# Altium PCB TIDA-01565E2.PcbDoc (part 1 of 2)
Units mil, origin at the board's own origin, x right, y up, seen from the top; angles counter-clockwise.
Board outline 1450 x 4000 mil, 4 copper layers (Top Layer L1, GND L2, Power L3, Bottom Layer L4), stack 62.4 mil thick; 92 components, 39 nets, 230 pads, 175 vias.
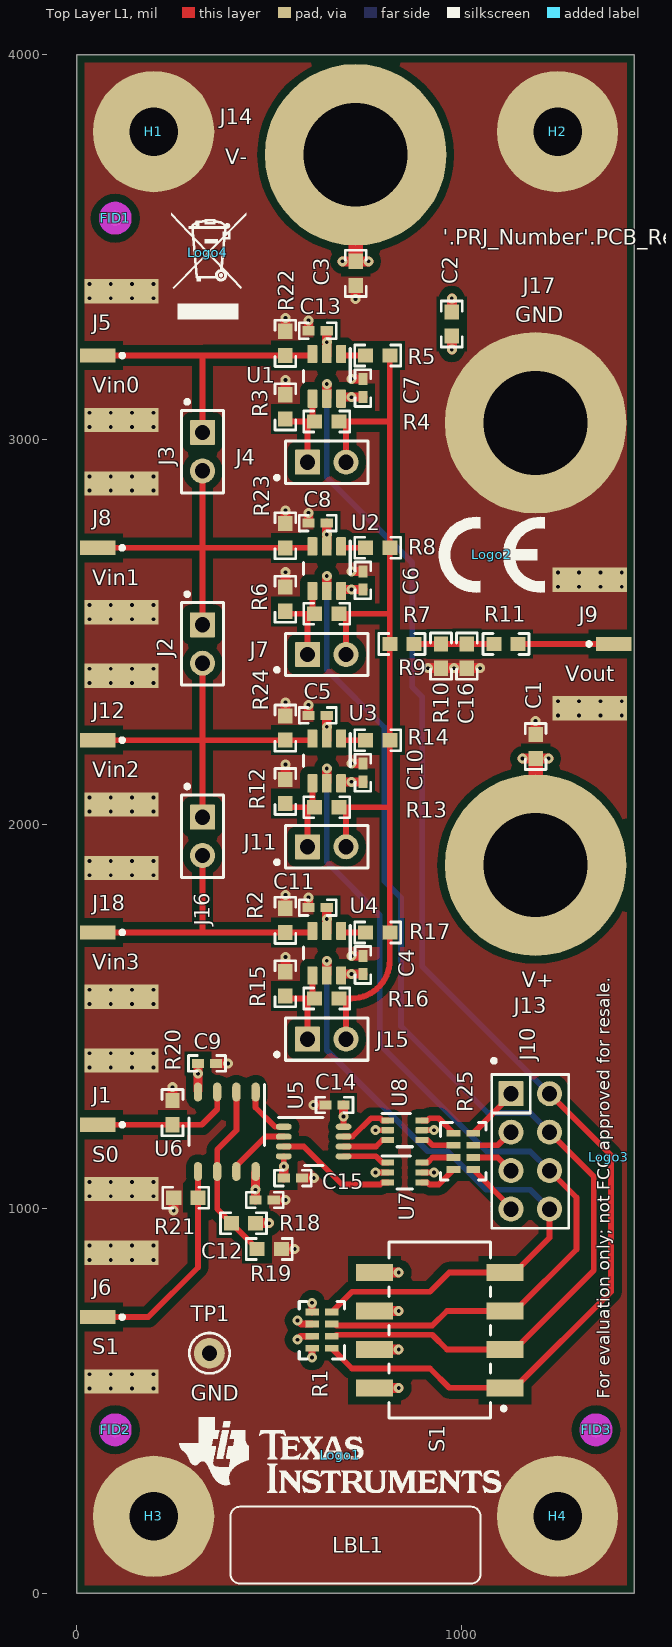
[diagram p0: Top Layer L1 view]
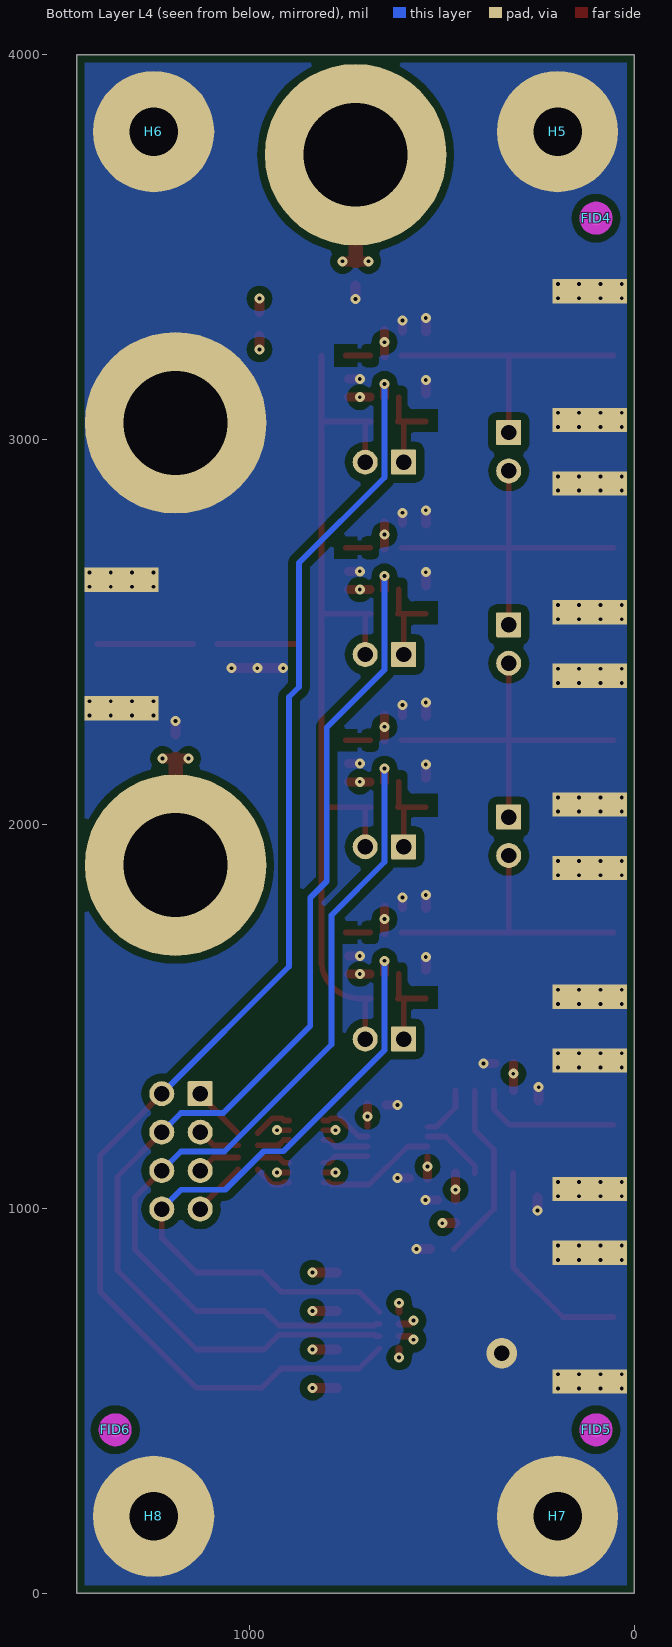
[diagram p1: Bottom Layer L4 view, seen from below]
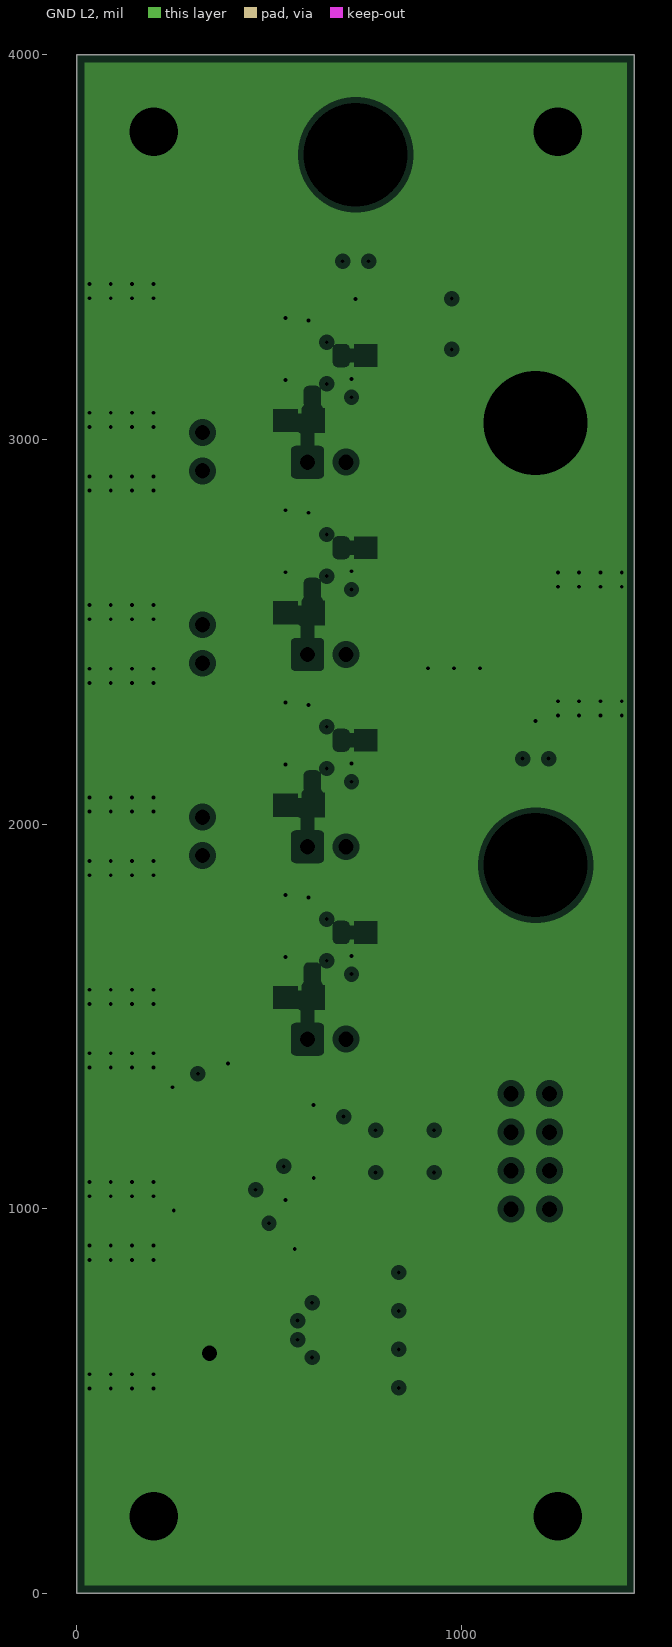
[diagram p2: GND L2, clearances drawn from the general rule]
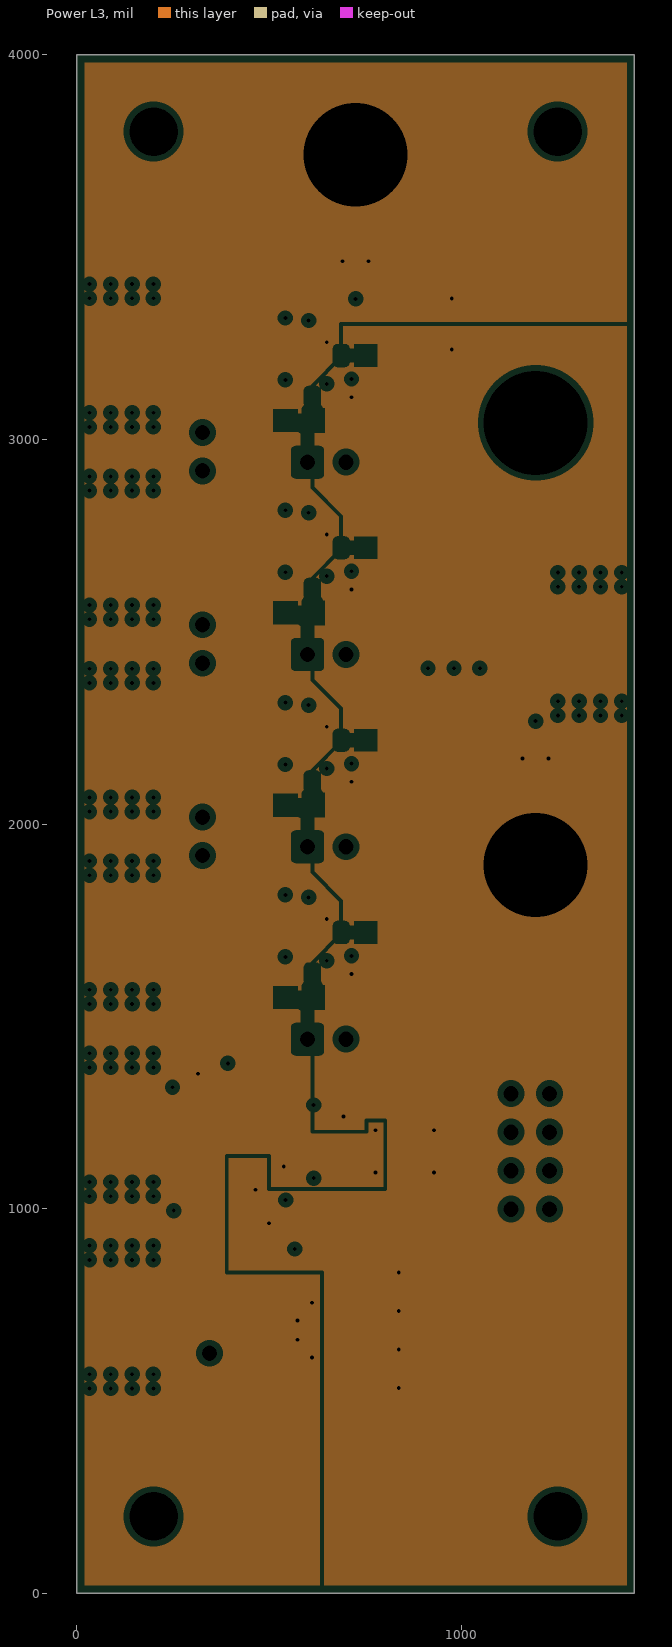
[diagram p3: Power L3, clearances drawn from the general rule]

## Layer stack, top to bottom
Top Solder: solder mask 0.4, Solder Resist, Dk 3.5
Top Layer L1: signal copper 1.4
Dielectric 1: core 8.4, FR-4 High Tg, Dk 4.6
GND L2: plane copper 1.4, net GND
Dielectric 2: prepreg 40, FR-4 High Tg, Dk 4.6
Power L3: plane copper 1.4, net (Multiple Nets)
Dielectric 3: core 8.4, FR-4 High Tg, Dk 4.6
Bottom Layer L4: signal copper 1.4
Bottom Solder: solder mask 0.4, Solder Resist, Dk 3.5

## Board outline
0,0 1450,0 1450,4000 0,4000

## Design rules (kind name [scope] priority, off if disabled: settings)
AcuteAngle [All] p1: minimum=4.50000000000000E+0001 checktracksonly=FALSE
AssemblyTestPointUsage [All] p1: valid=2
BoardOutlineClearance BoardOutlineClearance_1 [HasFootprint('Amphenol_901-10309')] p1: gap=20 ignorepadtopadclearanceinfootprint=FALSE except(7.87: SMDPad-OutlineEdge)
BoardOutlineClearance BoardOutlineClearance_MountingHoles [OnCopper and InComponentClass('Mounting Holes')] p2: gap=40 ignorepadtopadclearanceinfootprint=FALSE
BoardOutlineClearance BoardOutlineClearance_Poly [OnCopper and IsPoly] p3: gap=20 ignorepadtopadclearanceinfootprint=FALSE
BoardOutlineClearance [OnCopper and Not InComponentClass('Logo') and not InComponentClass('FiducialMark') and not InRegion(1000,500,4000,800) and not InPoly] p4: gap=20 ignorepadtopadclearanceinfootprint=FALSE
Clearance Clearance_FiducialMark [IsKeepOut and InComponentClass('FiducialMark') vs IsPad and InComponentClass('FiducialMark')] p1: gap=0 ignorepadtopadclearanceinfootprint=FALSE
Clearance Clearance_Keepouts [((IsTrack Or IsArc) And Not InPoly) And IsFree and IsKeepOut vs ((IsTrack Or IsArc) And Not InPoly) And IsFree and IsKeepOut] p2: gap=0 ignorepadtopadclearanceinfootprint=FALSE
Clearance Clearance_Poly [InPolygon] p3: gap=20 ignorepadtopadclearanceinfootprint=FALSE except(0: Arc-Hole Track-Hole SMDPad-Hole THPad-Hole Via-Hole Fill-Hole Poly-Hole Region-Hole Text-Hole)
Clearance [All] p4: gap=7.87 ignorepadtopadclearanceinfootprint=FALSE except(0: Arc-Hole Track-Hole SMDPad-Hole THPad-Hole Via-Hole Fill-Hole Poly-Hole Region-Hole Text-Hole)
ComponentClearance ComponentClearance_MountingHoles_FiducialMarks [InComponentClass('Mounting Holes') vs InComponentClass('FiducialMark')] p1: gap=50 collisioncheckmode=3 verticalgap=10 showdistances=FALSE
ComponentClearance ComponentClearance_Shunt [InComponentClass('Header') vs InComponentClass('Shunt')] p2: gap=0 collisioncheckmode=3 verticalgap=0 showdistances=FALSE
ComponentClearance ComponentClearance_Logo [InComponentClass('Logo')] p3: gap=0 collisioncheckmode=3 verticalgap=0 showdistances=FALSE
ComponentClearance ComponentClearance_ScrewToNut [(HasFootprint('NY PMS 440 0025 PH')) vs (HasFootprint('Keystone_1902C'))] p4: gap=5 collisioncheckmode=3 verticalgap=10 showdistances=FALSE
ComponentClearance ComponentClearance_MountingHoles [InComponentClass('Mounting Holes')] p5: gap=69 collisioncheckmode=3 verticalgap=100000 showdistances=FALSE
ComponentClearance ComponentClearance_SmallPassives [HasFootprint('0201*') or HasFootprint('0402*') or HasFootprint('0508') or HasFootprint('0603*') or HasFootprint('0612') or HasFootprint('0805*') or HasFootprint('0815*') or HasFootprint('0830*') or HasFootprint('1206*') or HasFootprint('1210*') or HasFootprint('1808*') or HasFootprint('1812*') or HasFootprint('1825*') or HasFootprint('2010*') or HasFootprint('2220*') or HasFootprint('2225*') or HasFootprint('2512*') or HasFootprint('2728*') or HasFootprint('3518*') or HasFootprint('DBV0006A*') vs HasFootprint('0201*') or HasFootprint('0402*') or HasFootprint('0508') or HasFootprint('0603*') or HasFootprint('0612') or HasFootprint('0805*') or HasFootprint('0815*') or HasFootprint('0830*') or HasFootprint('1206*') or HasFootprint('1210*') or HasFootprint('1808*') or HasFootprint('1812*') or HasFootprint('1825*') or HasFootprint('2010*') or HasFootprint('2220*') or HasFootprint('2225*') or HasFootprint('2512*') or HasFootprint('2728*') or HasFootprint('3518*') or HasFootprint('DBV0006A*')] p6: gap=14.96 collisioncheckmode=3 verticalgap=10 showdistances=FALSE
ComponentClearance ComponentClearance_THtoSMT [IsThruComponent vs IsSMTComponent] p7: gap=25 collisioncheckmode=3 verticalgap=30 showdistances=FALSE
ComponentClearance ComponentClearance_THtoTH [IsThruComponent vs IsThruComponent] p8: gap=30 collisioncheckmode=3 verticalgap=30 showdistances=FALSE
ComponentClearance [All] p9: gap=25 collisioncheckmode=3 verticalgap=10 showdistances=FALSE
DiffPairsRouting [All] p1: maxlimit=100 minlimit=10 mostfreqgap=10 toplayer_minwidth=15 toplayer_maxwidth=15 toplayer_prefwidth=15 bottomlayer_minwidth=15 bottomlayer_maxwidth=15 bottomlayer_prefwidth=15 maxuncoupledlength=1000
FabricationTestPointUsage TestPointUsage [All] p1: valid=2 allowmultiple=FALSE
FabricationTestpoint Testpoint [All] p1: side=3 testpointundercomponent=TRUE minsize=40 maxsize=100 preferedsize=60 minholesize=0 maxholesize=40 preferedholesize=32 testpointgrid=1 allowsidetop=TRUE allowsidebottom=TRUE usegrid=TRUE gridtolerance=0.01
FanoutControl Fanout_LCC [IsLCC] p1: bgadir=Out bgaviamode=Centered fanoutstyle=Auto fanoutdirection=Alternating viagrid=1 // Fanout_LCC (Default Rule)
FanoutControl Fanout_BGA [IsBGA] p2: bgadir=Out bgaviamode=Centered fanoutstyle=Auto fanoutdirection=Alternating viagrid=1 // Fanout_BGA (Default Rule)
FanoutControl Fanout_Default [All] p4: bgadir=Out bgaviamode=Centered fanoutstyle=Auto fanoutdirection=Alternating viagrid=1 // Fanout_Default (Default Rule)
FanoutControl Fanout_Small [(CompPinCount < 5)] p5: bgadir=Out bgaviamode=Centered fanoutstyle=Auto fanoutdirection=OutThenIn viagrid=1 // Fanout_Small (Default Rule)
HoleSize [All] p1: absolutevalues=TRUE maxlimit=270 minlimit=7.87 maxpercent=80.000 minpercent=20.000
MinimumAnnularRing MinimumAnnularRing_ThermalPadVias [IsVia and InAnyComponent] p1: minimumring=5.91
MinimumAnnularRing [All] p2: minimumring=8
MinimumSolderMaskSliver MinimumSolderMaskSliver_Logo [InComponentClass('Logo') vs InComponentClass('Logo')] p1: minsoldermaskwidth=0.7
MinimumSolderMaskSliver [All] p2: minsoldermaskwidth=3.94
PlaneClearance [All] p1: clearance=15
PlaneConnect [All] p1: planeconnectstyle=Direct reliefexpansion=10 reliefentries=4 reliefconductorwidth=10 reliefairgap=10
PolygonConnect [All] p1: connectstyle=Direct reliefconductorwidth=10 reliefentries=4 polygonreliefangle="90 Angle" airgapwidth=10
RoutingVias ThermalPadVias [IsVia and InAnyComponent] p1: holewidth=7.87 width=19.68 viastyle="Through Hole" minholewidth=7.87 minwidth=19.68 maxholewidth=12.99 maxwidth=23.62
RoutingVias [All] p2: holewidth=16 width=34 viastyle="Through Hole" minholewidth=7.87 minwidth=26 maxholewidth=40 maxwidth=65
SilkToBoardRegionClearance [Not ((IsComment or IsDesignator) And (Hide <> 'False')) and not InRegion(1000,500,4000,800)] p1:
SilkToSilkClearance SilkToSilkClearance_Pb-FreeLogo [(HasFootprint('Pb-Free_Overlay_Medium') OR HasFootprint('Pb-Free_Overlay_Small')) vs (HasFootprint('Pb-Free_Overlay_Medium') OR HasFootprint('Pb-Free_Overlay_Small'))] p1: silktosilkclearance=0
SilkToSilkClearance [All] p2: silktosilkclearance=4
SilkToSolderMaskClearance SilkToComponentPadClearance [(IsPad or IsFill or IsRegion) and InAnycomponent] p1: minsilkscreentomaskgap=5 clearancetoexposedcopper=TRUE
SilkToSolderMaskClearance "Silk to Solder Mask Opening" [All] p2: minsilkscreentomaskgap=4 clearancetoexposedcopper=FALSE
SolderMaskExpansion [All] p1: expansion=1.97
Width [All] p1: maxlimit=100 minlimit=6 preferedwidth=10 checkconnectedcopper=TRUE
14 further rules are at their usual default settings.

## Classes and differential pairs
component class AssemblyNote: ZZ1 ZZ2 ZZ3 ZZ4
component class FiducialMark: FID1 FID2 FID3 FID4 FID5 FID6
component class Header: J2 J3 J4 J7 J10 J11 J15 J16
component class Label: LBL1
component class Logo: Logo1
component class "Mounting Holes": H1 H2 H3 H4

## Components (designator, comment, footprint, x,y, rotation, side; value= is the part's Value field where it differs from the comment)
C1 "Capacitor" 0603 1193,2201.5 r90 top value=22uF
C2 "Capacitor" 0603 975,3300 r90 top value=22uF
C3 "Capacitor" 0603 725,3431.5 r270 top value=22uF
C4 "Capacitor" 0402 743.96,1633.35 r90 top value=0.1uF
C5 "Capacitor" 0402 626.38,2282.43 r180 top value=0.1uF
C6 "Capacitor" 0402 743.96,2633.35 r90 top value=0.1uF
C7 "Capacitor" 0402 743.96,3133.35 r90 top value=0.1uF
C8 "Capacitor" 0402 626.38,2782.43 r180 top value=0.1uF
C9 "Capacitor" 0402 338.58,1377.57 r0 top value=0.1uF
C10 "Capacitor" 0402 743.96,2133.35 r90 top value=0.1uF
C11 "Capacitor" 0402 626.38,1782.43 r180 top value=0.1uF
C12 "Capacitor" 0402 488.62,1022.43 r0 top value=0.1uF
C13 "Capacitor" 0402 626.38,3282.43 r180 top value=0.1uF
C14 "Capacitor" 0402 670.13,1269.41 r0 top value=0.1uF
C15 "Capacitor" 0402 561.87,1079.41 r180 top value=0.1uF
C16 "Capacitor" 0603 1014.34,2436.5 r270 top value=330pF
FID1 "Fiducial" Fiducial10-20 100,3575 r0 top
FID2 "Fiducial" Fiducial10-20 100,425 r0 top
FID3 "Fiducial" Fiducial10-20 1350,425 r0 top
FID4 "Fiducial" Fiducial10-20 100,3575 r0 bottom
FID5 "Fiducial" Fiducial10-20 100,425 r0 bottom
FID6 "Fiducial" Fiducial10-20 1350,425 r0 bottom
H1 "NY PMS 440 0025 PH" "NY PMS 440 0025 PH" 200,3800 r0 top locked
H2 "NY PMS 440 0025 PH" "NY PMS 440 0025 PH" 1250,3800 r0 top locked
H3 "NY PMS 440 0025 PH" "NY PMS 440 0025 PH" 200,200 r0 top locked
H4 "NY PMS 440 0025 PH" "NY PMS 440 0025 PH" 1250,200 r0 top locked
H5 "Nut" Keystone_1902C 200,3800 r180 bottom locked
H6 "Nut" Keystone_1902C 1250,3800 r180 bottom locked
H7 "Nut" Keystone_1902C 200,200 r180 bottom locked
H8 "Nut" Keystone_1902C 1250,200 r180 bottom locked
J1 "S0" Amphenol_901-10309 0,1218 r90 top
J2 "TSW-102-07-G-S" TSW-102-07-X-S 327,2468 r270 top
J3 "TSW-102-07-G-S" TSW-102-07-X-S 327,2968 r270 top
J4 "TSW-102-07-G-S" TSW-102-07-X-S 650,2940.76 r0 top
J5 "Vin0" Amphenol_901-10309 0,3218 r90 top
J6 "S1" Amphenol_901-10309 0,718 r90 top
J7 "TSW-102-07-G-S" TSW-102-07-X-S 650,2440.76 r0 top
J8 "Vin1" Amphenol_901-10309 0,2718 r90 top
J9 "Vout" Amphenol_901-10309 1450,2468 r270 top
J10 "TSW-104-07-G-D" TSW-104-07-G-D 1179,1148.82 r270 top
J11 "TSW-102-07-G-S" TSW-102-07-X-S 650,1940.76 r0 top
J12 "Vin2" Amphenol_901-10309 0,2218 r90 top
J13 "V+" Keystone_6095 1193,1893 r0 top
J14 "V-" Keystone_6095 725,3740 r0 top
J15 "TSW-102-07-G-S" TSW-102-07-X-S 650,1440.76 r0 top
J16 "TSW-102-07-G-S" TSW-102-07-X-S 327,1968 r270 top
J17 "GND" Keystone_6095 1193,3043 r0 top
J18 "Vin3" Amphenol_901-10309 0,1718 r90 top
LBL1 "Size: 0.65\" x 0.20 \"" Label_650x200 724.79,125 r0 top
Logo1 "Texas Instruments" TI_Stacked_Overlay_Small 685,359 r0 top
Logo2 "CE Mark" CE_Mark_5mm 1079,2700 r0 top
Logo3 "FCC disclaimer" FCC_disclaimer 1383,1133 r90 top
Logo4 "WEEE logo" WEEE_Minimum 341,3485 r0 top
R1 "RES_ARRAY_4x1" TC164 637.5,684 r180 top value=10k
R2 "Resistor" 0603 542.46,1749.5 r270 top value=49.9
R3 "RT0603BRD072KL" 0603 542.46,3084.47 r270 top value=2.00k
R4 "RT0603BRD072KL" 0603 650,3046.4 r0 top value=2.00k
R5 "Resistor" 0603 782.44,3218 r0 top value=49.9
R6 "RT0603BRD072KL" 0603 542.46,2584.47 r270 top value=2.00k
R7 "RT0603BRD072KL" 0603 650,2546.4 r0 top value=2.00k
R8 "Resistor" 0603 782.44,2718 r0 top value=49.9
R9 "RC0603FR-071K96L" 0603 845.44,2468 r0 top value=1.96k
R10 "Resistor" 0603 947,2436.5 r90 top value=51.1
R11 "RC0603JR-070RL" 0603 1115.97,2468 r0 top value=0
R12 "RT0603BRD072KL" 0603 542.46,2084.47 r270 top value=2.00k
R13 "RT0603BRD072KL" 0603 650,2043.77 r0 top value=2.00k
R14 "Resistor" 0603 782.44,2218 r0 top value=49.9
R15 "RT0603BRD072KL" 0603 542.46,1584.47 r270 top value=2.00k
R16 "RT0603BRD072KL" 0603 650,1546.4 r0 top value=2.00k
R17 "Resistor" 0603 782.44,1718 r0 top value=49.9
R18 "Resistor" 0603 433.5,962 r180 top value=100k
R19 "Resistor" 0603 500.5,895 r180 top value=49.9
R20 "Resistor" 0603 249,1249.5 r270 top value=49.9
R21 "Resistor" 0603 283.5,1028.5 r0 top value=49.9
R22 "Resistor" 0603 542.46,3249.5 r270 top value=49.9
R23 "Resistor" 0603 542.46,2749.5 r270 top value=49.9
R24 "Resistor" 0603 542.46,2249.5 r270 top value=49.9
R25 "RES_ARRAY_4x1" TC164 1004.98,1148.81 r0 top value=10k
S1 "SW_4SPST" SW_219-4LPST 943.5,684 r180 top
TP1 "GND" Keystone5001 345,624 r90 top
U1 "OPA837IDBVR" DBV0006A_M 650,3163.87 r270 top
U2 "OPA837IDBVR" DBV0006A_M 650,2663.87 r270 top
U3 "OPA837IDBVR" DBV0006A_M 650,2163.87 r270 top
U4 "OPA837IDBVR" DBV0006A_M 650,1663.87 r270 top
U5 "SN74LVC1G139DCTR" DCT0008A_N 616,1174.41 r0 top
U6 "TI-AMP-D6-2-8_D" D0008A_L 390,1200 r270 top
U7 "SN74LVC2G04DCKT" DCK0006A_N 853,1093.81 r0 top
U8 "SN74LVC2G04DCKT" DCK0006A_N 853,1203.81 r0 top
ZZ1 "This Assembly Note is for PCB labels only" AssemblyNoteLabel 185,4484 r0 top
ZZ2 "These assemblies are ESD sensitive, ESD precautions shall be observed." AssemblyNote 185,4375.11 r0 top
ZZ3 "These assemblies must be clean and free from flux and all contaminants. Use of no clean flux is not acceptable." AssemblyNote 185,4286.56 r0 top
ZZ4 "These assemblies must comply with workmanship standards IPC-A-610 Class 2, unless otherwise specified." AssemblyNote 185,4198 r0 top

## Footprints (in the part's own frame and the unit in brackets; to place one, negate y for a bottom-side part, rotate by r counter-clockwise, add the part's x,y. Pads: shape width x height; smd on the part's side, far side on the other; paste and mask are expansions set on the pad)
0402 [mm] "0402 from SM-752 data"
  rect 0.8x0.6 smd: 1(-0.6,0) 2(0.6,0)
  silkscreen extent -1.22,-0.52 1.22,0.52, body extent -0.55,-0.3 0.55,0.3, height 0.6
0603 [mm] "0603 from SM-752 data"
  rect 1x0.95 smd: 1(-0.8,0) 2(0.8,0)
  silkscreen extent -1.52,-0.69 1.52,0.69, body extent -0.87,-0.47 0.87,0.47, height 1
Amphenol_901-10309 [mm] "SMA JACK 50 OHM EDGE MNT, SMT"
  rect 0.94x2.35 smd: 1(0,-1.375)
  rect 1.6x4.9 smd: 2(-4.25,-2.95) 3(4.25,-2.95)
  rect 1.6x4.9 smd far side: 4(-4.25,-2.95) 5(4.25,-2.95)
  silkscreen extent -0.12,-3.13 0.12,-2.88, body extent -4.76,-5.25 4.76,9.03, height 4.08
AssemblyNote [mil] "Assembly Note"
AssemblyNoteLabel [mil] "Assembly Note for PCB Labels"
CE_Mark_5mm [mil] "Minimum text height for CE Mark"
  silkscreen extent -138,-98 138,98
D0008A_L [mm] "SOIC, 8-Leads, Body 4.9x3.9mm, Pitch 1.27mm, IPC High Density"
  oval 1.25x0.55 smd: 1(-2.625,1.905) 2(-2.625,0.635) 3(-2.625,-0.635) 4(-2.625,-1.905) 5(2.625,-1.905) 6(2.625,-0.635) 7(2.625,0.635) 8(2.625,1.905)
  silkscreen extent -3.1,-2.5 0.9,2.5, body extent -3,-2.45 3,2.45, height 1.63
DBV0006A_M [mm] "SOT23, 6-Leads, Body 2.9x1.6mm, Pitch 0.95mm, Lead Span 2.8mm, IPC Low Density"
  rrect15% 1.2x0.65 smd: 1(-1.475,0.95) 2(-1.475,0) 3(-1.475,-0.95) 4(1.475,-0.95) 5(1.475,0) 6(1.475,0.95)
  silkscreen extent -1.83,-1.55 0.38,1.55, body extent -1.42,-1.46 1.42,1.46, height 1.12
DCK0006A_N [mm] "SOT23, 6-Leads, Body 2x1.3mm, Pitch 0.65mm, Lead Span 2.1mm, IPC Medium Density"
  rrect25% 0.85x0.4 smd: 1(-1.125,0.65) 2(-1.125,0) 3(-1.125,-0.65) 4(1.125,-0.65) 5(1.125,0) 6(1.125,0.65)
  silkscreen extent -1.5,-1.09 0.51,1.09, body extent -1.14,-1 1.14,1, height 0.95
DCT0008A_N [mm] "TSOP, 8-Leads, Body 3x2.8mm, Pitch 0.65mm, IPC Medium Density"
  oval 1.05x0.4 smd: 1(-1.975,0.975) 2(-1.975,0.325) 3(-1.975,-0.325) 4(-1.975,-0.975) 5(1.975,-0.975) 6(1.975,-0.325) 7(1.975,0.325) 8(1.975,0.975)
  silkscreen extent -2.32,-1.57 0.6,1.58, body extent -2.01,-1.47 2.01,1.48, height 1.3
FCC_disclaimer [mil]
Fiducial10-20 [mm]
  round 1 smd mask+0.5: 1(0,0)
  Top Layer L1 keep-out circle w1.178: c0,0 r0.5
Keystone5001 [mil] "For Keystone 500x miniature loop terminals"
  round 80 hole 40: 1(0,0)
  silkscreen extent -52,-52 52,52, body extent -49,-49 49,49, height 182
Keystone_1902C [mil] "Hex Standoff, 4-40 threaded, nylon"
  round 1 on Mech4: 0(0,0)
  body extent -145,-126 146,126, height 501
Keystone_6095 [mm] "Banana Jack Uninsulated Standard Type"
  round 12 hole 6.858: 1(0,0)
  body extent -4.77,-5.5 4.75,5.49, height 2.39
Label_650x200 [mil] "Thermal Transfer Label"
  round 1 on Mech13: 0(0,0)
  silkscreen extent -325,-100 325,100, body extent -325,-100 325,100, height 1
"NY PMS 440 0025 PH" [mm] "4-40 nylon screw and mounting hole"
  round 8 hole 3.2: 1(0,0)
  body extent -3.3,-3.3 3.3,3.3, height 2.69
SW_219-4LPST [mil] "SMD, 8-Leads, Body 11.93x6.95mm, Pitch 2.54mm"
  rect 96x44 smd: 1(-169.5,150) 2(-169.5,50) 3(-169.5,-50) 4(-169.5,-150) 5(169.5,-150) 6(169.5,-50) 7(169.5,50) 8(169.5,150)
  silkscreen extent -171,-229 132,229, body extent -195,-229 195,229, height 169
TC164 [mm] "SMD, 8-Leads, Body 3.2x1.6mm, Pitch 0.8mm"
  rect 0.9x0.45 smd: 1(-0.65,1.2) 2(-0.65,0.4) 3(-0.65,-0.4) 4(-0.65,-1.2) 5(0.65,-1.2) 6(0.65,-0.4) 7(0.65,0.4) 8(0.65,1.2)
  silkscreen extent -1.5,-1.9 1.5,1.9, body extent -0.87,-1.68 0.87,1.68, height 0.71
TI_Stacked_Overlay_Small [mil]
  silkscreen extent -418,-98 418,98
TSW-102-07-X-S [mm] "Samtec 100 mil 1x2 head, 230 mil above insulator"
  rrect6% 1.65x1.65 hole 1.016: 1(-1.27,0)
  round 1.65 hole 1.016: 2(1.27,0)
  silkscreen extent -3.42,-1.4 2.72,1.4, body extent -2.54,-1.27 2.54,1.27, height 8.38
TSW-104-07-G-D [mm] "Samtec 100mil, 2x4, 230 mil above insulator"
  rrect6% 1.65x1.65 hole 1.016: 1(-3.81,-1.27)
  round 1.65 hole 1.016: 2(-3.81,1.27) 3(-1.27,-1.27) 4(-1.27,1.27) 5(1.27,-1.27) 6(1.27,1.27) 7(3.81,-1.27) 8(3.81,1.27)
  silkscreen extent -6.1,-2.54 5.08,2.54, body extent -5.08,-2.54 5.08,2.54, height 8.38
WEEE_Minimum [mil] "WEEElie bin"
  silkscreen extent -95,-172 99,104

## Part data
C1 C2 C3: library part CMP-0007158-5, "CAP, CERM, 22 uF, 10 V, +/- 20%, X5R, 0603", Cap_Case=0603, Manufacturer=MuRata, PartNumber=GRM187R61A226ME15D, Supplier Part Number 1=490-13243-1-ND, TempCo=X5R, Tolerance_%=20%, Value1=Unknown, Value2=10V, ValueDisplayed=22uF
C4 C5 C6 C7 C8 C9 C10 C11 C12 C13 C14 C15: library part CMP-0006259-2, "CAP, CERM, 0.1 uF, 10 V, +/- 10%, X5R, 0402", Cap_Case=0402, Manufacturer=TDK, PartNumber=C1005X5R1A104K050BA, Supplier Part Number 1=445-1265-1-ND, TempCo=X5R, Tolerance_%=10%, Value1=Unknown, Value2=10V, ValueDisplayed=0.1uF
C16: library part CMP-0006784-4, "CAP, CERM, 330 pF, 50 V, +/- 5%, C0G/NP0, 0603", Cap_Case=0603, Manufacturer=AVX, PartNumber=06035A331JAT2A, Supplier Part Number 1=478-1181-1-ND, TempCo=C0G/NP0, Tolerance_%=5%, Value1="0.071 ohm", Value2=50V, ValueDisplayed=330pF
FID1 FID2 FID3 FID4 FID5 FID6: library part CMP-0077181-1, "Fiducial mark.  There is nothing to buy or mount.", Manufacturer=N/A
H1 H2 H3 H4: library part CMP-0003617-1, "Machine Screw, Round, #4-40 x 1/4, Nylon, Philips panhead", Manufacturer="B&F Fastener Supply", Supplier Part Number 1=H542-ND
H5 H6 H7 H8: library part CMP-0003610-1, "Standoff, Hex, 0.5\"L #4-40 Nylon", Manufacturer=Keystone, PartNumber=1902C, Supplier Part Number 1=36-1902C-ND
J1 J5 J6 J8 J9 J12 J18: library part CMP-0055840-1, "SMA JACK 50 OHM EDGE MNT, SMT", Manufacturer="Amphenol-Tuchel Electronics", PartNumber=901-10309, Supplier Part Number 1=ARF1744-ND
J2 J3 J4 J7 J11 J15 J16: library part CMP-0075405-1, "Header, 100mil, 2x1, Gold, TH", Color=Black, Current_A=6.3A, Manufacturer=Samtec, Supplier Part Number 1=SAM1029-02-ND, Voltage_V=550V
J10: library part CMP-0075408-1, "Header, 100mil, 4x2, Gold, TH", Color=Black, Current_A=6.3A, Manufacturer=Samtec, Supplier Part Number 1=SAM1028-04-ND, Voltage_V=550V
J13 J14 J17: library part CMP-0055169-2, "Standard Banana Jack, Uninsulated", Manufacturer=Keystone, PartNumber=6095, Supplier Part Number 1=36-6095-ND
LBL1: library part CMP-0003625-1, "Thermal Transfer Printable Labels, 0.650\" W x 0.200\" H - 10,000 per roll", Manufacturer=Brady, PartNumber=THT-14-423-10, Supplier Part Number 1=97C5133
Logo1: library part CMP-0074838-1, "Texas Instrument Corporate Signature"
Logo2: library part CMP-0074844-1
Logo3: library part CMP-0074847-1, "FCC_disclaimer"
Logo4: library part CMP-0074769-1
R1 R25: library part CMP-0015378-3, "RES, 10 k, 5%, 0.0625 W, 3.2x1.6mm", Manufacturer="Yageo America", PartNumber=TC164-JR-0710KL, Power_W=62.5mW, Supplier Part Number 1=TC164J-10KCT-ND, TempCo="200 ppm/C", Tolerance_%=5%, Value2=0.0625W, Value_Code=10k0, ValueDisplayed=10k
R2 R5 R8 R14 R17 R19 R20 R21 R22 R23 R24: library part CMP-0022707-2, "RES, 49.9, 1%, 0.1 W, AEC-Q200 Grade 0, 0603", Manufacturer=Panasonic, PartNumber=ERJ-3EKF49R9V, Power_W=100mW, Supplier Part Number 1=P49.9HCT-ND, TempCo="100 ppm/C", Tolerance_%=1%, Value2=0.1W, Value_Code=49R9, ValueDisplayed=49.9
R3 R4 R6 R7 R12 R13 R15 R16: library part CMP-0024089-3, "RES, 2.00 k, 0.1%, 0.1 W, 0603", Manufacturer="Yageo America", Power_W=100mW, Supplier Part Number 1=603-RT0603BRD072KL, TempCo="25 ppm/C", Tolerance_%=0.1%, Value2=0.1W, Value_Code=2k00, ValueDisplayed=2.00k
R9: library part CMP-0022894-3, "RES, 1.96 k, 1%, 0.1 W, 0603", Manufacturer="Yageo America", Power_W=100mW, Supplier Part Number 1=311-1.96KHRCT-ND, TempCo="200 ppm/C", Tolerance_%=1%, Value2=0.1W, Value_Code=1k96, ValueDisplayed=1.96k
R10: library part CMP-0023168-3, "RES, 51.1, 1%, 0.1 W, 0603", Manufacturer="Yageo America", PartNumber=RC0603FR-0751R1L, Power_W=100mW, Supplier Part Number 1=311-51.1HRCT-ND, TempCo="200 ppm/C", Tolerance_%=1%, Value2=0.1W, Value_Code=51R1, ValueDisplayed=51.1
R11: library part CMP-0025885-3, "RES, 0, 5%, 0.1 W, 0603", Manufacturer="Yageo America", Power_W=100mW, Supplier Part Number 1=311-0.0GRCT-ND, TempCo="200 ppm/C", Tolerance_%=5%, Value2=0.1W, Value_Code=0000, ValueDisplayed=0
R18: library part CMP-0023630-3, "RES, 100 k, 0.1%, 0.1 W, 0603", Manufacturer="Yageo America", PartNumber=RT0603BRD07100KL, Power_W=100mW, Supplier Part Number 1=603-RT0603BRD07100KL, TempCo="25 ppm/C", Tolerance_%=0.1%, Value2=0.1W, Value_Code=100k
S1: library part CMP-0002176-2, "Switch, SPST 4 Pos, Top Actuated, SMT", CurrentRating_mA=100A, Manufacturer="CTS Electrocomponents", PartNumber=219-4LPST, Supplier Part Number 1=CT2194LPST-ND
TP1: library part CMP-0055138-1, "Test Point, Miniature, Black, TH", Color=Black, Manufacturer=Keystone, PartNumber=5001, Supplier Part Number 1=36-5001-ND
U1 U2 U3 U4: library part CMP-0013237-2, "Low Power, Precision, 105MHz, Voltage Feedback Op Amp, DBV0006A (SOT-6)", Alternate Manufacturer="Texas Instruments", Alternate PartNumber=OPA837IDBVT
U5: library part CMP-0050973-1, "2-Line-to-4-Line Decoder, DCT0008A, LARGE T&R", F @ Nom Voltage(Max)(Mhz)=150, Generic Part Number=SN74LVC1G139, ICC @ Nom Voltage(Max)(mA)=0.01, Manufacturer="Texas Instruments", Operating Temperature Range(C)="-40 to 85", Rating=Catalog, tpd @ Nom Voltage(Max)(ns)=16.5,7.5,4.9,3.6, Voltage(Nom)(V)=1.8,2.5,3.3,5
U6: library part CMP-0043405-1, "Dual High-Performance, Low-Voltage Operational Amplifier, 2 to 5 V, -40 to 85 degC, 8-pin SOIC (D8), Green (RoHS & no Sb/Br)", Manufacturer="Texas Instruments", PartNumber=TLV2362ID, Total Supply Voltage(Max)(+5V is 5, +/-5V is 10)=5, Total Supply Voltage(Min)(+5V is 5, +/-5V is 10)=2
U7 U8: library part CMP-0051888-2, "Dual Inverter, DCK0006A, SMALL T&R", F @ Nom Voltage(Max)(Mhz)=150, Generic Part Number=SN74LVC2G04, ICC @ Nom Voltage(Max)(mA)=0.01, Manufacturer="Texas Instruments", Operating Temperature Range(C)="-40 to 125", Rating=Catalog, tpd @ Nom Voltage(Max)(ns)=8,4.9,4.6,3.7, Voltage(Nom)(V)=1.8,2.5,3.3,5
ZZ1: library part CMP-0003616-3
ZZ2: library part CMP-0077236-1
ZZ3: library part CMP-0077237-1
ZZ4: library part CMP-0077238-1

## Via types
v1: diameter 26, hole 10, Top Layer L1 to Bottom Layer L4, tented both sides, 175 vias

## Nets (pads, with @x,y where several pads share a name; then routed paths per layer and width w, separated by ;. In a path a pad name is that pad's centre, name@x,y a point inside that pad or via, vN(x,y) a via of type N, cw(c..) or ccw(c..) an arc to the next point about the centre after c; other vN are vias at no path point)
GND: C1.2 C3.2 C4.2 C5.2 C6.2 C7.2 C8.2 C9.2 C10.2 C11.2 C12.2 C13.2 C14.1 C15.1 C16.2 H1.1 H2.1 H3.1 H4.1 J1.2 J1.3 J1.4 J1.5 J5.2 J5.3 J5.4 J5.5 J6.2 J6.3 J6.4 J6.5 J8.2 J8.3 J8.4 J8.5 J9.2 J9.3 J9.4 J9.5 J12.2 J12.3 J12.4 J12.5 J17.1 J18.2 J18.3 J18.4 J18.5 R2.1 R3.1 R6.1 R10.1 R12.1 R15.1 R19.1 R20.1 R21.1 R22.1 R23.1 R24.1 TP1.1 | length 933.3
  Top Layer L1 w23.62: C9.2@362.2,1377.57 v1(392.92,1377.57) ; C12.2@512.24,1022.43 v1(542.96,1022.43) ; C15.1@585.49,1079.41 v1(616.2,1079.41) ; C11.2@602.76,1782.43 v1(602.76,1809.21) ; C5.2@602.76,2282.43 v1(602.76,2309.21) ; C8.2@602.76,2782.43 v1(602.76,2809.21) ; C13.2@602.76,3282.43 v1(602.76,3309.21) ; v1(615.8,1269.41) C14.1@646.51,1269.41 ; v1(714.18,1656.98) C4.2@743.96,1656.98 ; v1(714.18,2156.98) C10.2@743.96,2156.98 ; v1(714.18,2656.98) C6.2@743.96,2656.98 ; v1(714.18,3156.98) C7.2@743.96,3156.98
  Top Layer L1 w26: R20.1@249,1280.99 v1(249,1315.64) ; v1(252.01,994.83) R21.1@252.01,1028.5 ; R19.1@532,895 v1(566.65,895) ; R15.1@542.46,1619.91 v1(542.46,1654.56) ; R2.1@542.46,1780.99 v1(542.46,1815.64) ; R12.1@542.46,2119.91 v1(542.46,2154.56) ; R24.1@542.46,2280.99 v1(542.46,2315.64) ; R6.1@542.46,2619.9 v1(542.46,2654.56) ; R23.1@542.46,2780.99 v1(542.46,2815.64) ; R3.1@542.46,3119.91 v1(542.46,3154.56) ; R22.1@542.46,3280.99 v1(542.46,3315.64) ; v1(725,3365.36) C3.2@725,3400.01 ; v1(913.33,2405.01) R10.1@947,2405.01 v1(980.67,2405.01) C16.2@1014.34,2405.01 v1(1048.01,2405.01) ; C1.2@1193,2232.99 v1(1193,2267.64)
  other v1: 33.04,532.18 88.44,532.18 143.84,532.18 199.24,532.18 33.04,569.17 88.44,569.17 143.84,569.17 199.24,569.17 33.04,866.83 88.44,866.83 143.84,866.83 199.24,866.83 33.04,903.82 88.44,903.82 143.84,903.82 199.24,903.82 33.04,1032.18 88.44,1032.18 143.84,1032.18 199.24,1032.18 33.04,1069.17 88.44,1069.17 143.84,1069.17 199.24,1069.17 33.04,1366.83 88.44,1366.83 143.84,1366.83 199.24,1366.83 33.04,1403.82 88.44,1403.82 143.84,1403.82 199.24,1403.82 33.04,1532.18 88.44,1532.18 143.84,1532.18 199.24,1532.18 33.04,1569.17 88.44,1569.17 143.84,1569.17 199.24,1569.17 33.04,1866.83 88.44,1866.83 143.84,1866.83 199.24,1866.83 33.04,1903.82 88.44,1903.82 143.84,1903.82 199.24,1903.82 33.04,2032.18 88.44,2032.18 143.84,2032.18 199.24,2032.18 33.04,2069.17 88.44,2069.17 143.84,2069.17 199.24,2069.17 1250.76,2282.18 1306.16,2282.18 1361.56,2282.18 1416.96,2282.18 1250.76,2319.17 1306.16,2319.17 1361.56,2319.17 1416.96,2319.17 33.04,2366.83 88.44,2366.83 143.84,2366.83 199.24,2366.83 33.04,2403.82 88.44,2403.82 143.84,2403.82 199.24,2403.82 33.04,2532.18 88.44,2532.18 143.84,2532.18 199.24,2532.18 33.04,2569.17 88.44,2569.17 143.84,2569.17 199.24,2569.17 1250.76,2616.83 1306.16,2616.83 1361.56,2616.83 1416.96,2616.83 1250.76,2653.82 1306.16,2653.82 1361.56,2653.82 1416.96,2653.82 33.04,2866.83 88.44,2866.83 143.84,2866.83 199.24,2866.83 33.04,2903.82 88.44,2903.82 143.84,2903.82 199.24,2903.82 33.04,3032.18 88.44,3032.18 143.84,3032.18 199.24,3032.18 33.04,3069.17 88.44,3069.17 143.84,3069.17 199.24,3069.17 33.04,3366.83 88.44,3366.83 143.84,3366.83 199.24,3366.83 33.04,3403.82 88.44,3403.82 143.84,3403.82 199.24,3403.82
NetC16_1: C16.1 R9.2 R10.2 R11.1 | length 207.5
  Top Layer L1 w15: R9.2@876.93,2468 R10.2@947,2468 R11.1@1084.47,2468
NetJ1_1: J1.1 R20.2 U6.3 | length 376.6
  Top Layer L1 w15: J1.1@54.13,1218 324.73,1218 365,1258.27 U6.3@365,1307.28
NetJ2_1: J2.1 J3.2 J8.1 R23.2 U2.3 | length 951.8
  Top Layer L1 w15: J8.1@54.13,2718 U2.3@605.91,2718 ; J2.1@327,2518 327,2718 J3.2@327,2918
NetJ2_2: J2.2 J12.1 J16.1 R24.2 U3.3 | length 951.8
  Top Layer L1 w15: J12.1@54.13,2218 U3.3@605.91,2218 ; J16.1@327,2018 327,2218 J2.2@327,2418
NetJ3_1: J3.1 J5.1 R22.2 U1.3 | length 751.8
  Top Layer L1 w15: J5.1@54.13,3218 U1.3@605.91,3218 ; J3.1@327,3018 327,3218
NetJ4_1: J4.1 R3.2 R4.1 U1.4 | length 241.1
  Top Layer L1 w15: R3.2@542.46,3046.4 R4.1@614.57,3046.4 ; J4.1@600,2940.76 R4.1@600,3046.4 ; R4.1@612.6,3046.4 U1.4@612.6,3109.73
NetJ4_2: J4.2 J7.2 J11.2 J15.2 R4.2 R5.2 R7.2 R8.2 R9.1 R13.2 R14.2 R16.2 R17.2 | length 2562.6
  Top Layer L1 w15: R16.2@685.43,1546.4 713.94,1546.4 ccw(c713.94,1646.4) 813.94,1646.4 R17.2@813.94,1718 R14.2@813.94,2218 R8.2@813.94,2718 R5.2@813.94,3218 ; R13.2@685.43,2043.77 813.94,2043.77 ; R7.2@685.43,2546.4 813.94,2546.4 ; R4.2@685.43,3046.4 813.94,3046.4 ; J15.2@700,1440.76 R16.2@700,1546.4 ; J11.2@700,1940.76 R13.2@700,2043.77 ; J7.2@700,2440.76 R7.2@700,2546.4 ; J4.2@700,2940.76 R4.2@700,3046.4
NetJ6_1: J6.1 R21.2 U6.5 | length 560
  Top Layer L1 w15: J6.1@54.13,718 186,718 315,847 315,1043.71 U6.5@315,1092.72
NetJ7_1: J7.1 R6.2 R7.1 U2.4 | length 241.1
  Top Layer L1 w15: R6.2@542.46,2546.4 R7.1@614.57,2546.4 ; J7.1@600,2440.76 R7.1@600,2546.4 ; R7.1@612.6,2546.4 U2.4@612.6,2609.73
NetJ9_1: J9.1 R11.2 | length 248.4
  Top Layer L1 w15: R11.2@1147.46,2468 J9.1@1395.87,2468
NetJ10_1: J10.1 R25.8 | length 143.5
  Top Layer L1 w15: R25.8@1030.57,1196.06 1129,1294.48 J10.1@1129,1298.82
NetJ10_2: J10.2 R1.1 S1.1 U1.5 | length 3573.2
  Top Layer L1 w15: R1.1@663.09,636.76 715.85,584 918.5,584 968.5,534 S1.1@1113,534 1139,534 1389,784 1389,1138.82 J10.2@1229,1298.82
  Top Layer L1 w23.62: U1.5@650,3109.73 v1(650,3144.39)
  Bottom Layer L4 w15: v1(650,3144.39) 650,2901 872,2679 872,2356 898,2330 898,1629.82 J10.2@1229,1298.82
NetJ10_3: J10.3 R25.7 | length 112.6
  Top Layer L1 w15: R25.7@1030.57,1164.56 1094.75,1164.56 J10.3@1129,1198.82
NetJ10_4: J10.4 R1.2 S1.2 U2.5 | length 2975.1
  Top Layer L1 w15: R1.2@663.09,668.25 671.09,668.25 675,672.17 924.42,672.17 962.58,634 S1.2@1113,634 1139,634 1344,839 1344,1083.82 J10.4@1229,1198.82
  Top Layer L1 w23.62: U2.5@650,2609.73 v1(650,2644.39)
  Bottom Layer L4 w15: v1(650,2644.39) 650,2401 800,2251 800,1851 843,1808 843,1475 1069.18,1248.82 1179,1248.82 J10.4@1229,1198.82
NetJ10_5: J10.5 R25.6 | length 112.6
  Top Layer L1 w15: R25.6@1030.57,1133.07 1094.75,1133.07 J10.5@1129,1098.82
NetJ10_6: J10.6 R1.3 S1.3 U3.5 | length 2339.6
  Top Layer L1 w15: R1.3@663.09,699.75 671.09,699.75 675,695.83 924.42,695.83 962.58,734 S1.3@1113,734 1139,734 1299,894 1299,1028.82 J10.6@1229,1098.82
  Top Layer L1 w23.62: U3.5@650,2109.73 v1(650,2144.39)
  Bottom Layer L4 w15: v1(650,2144.39) 650,1901 788,1763 788,1427 1066.18,1148.82 1179,1148.82 J10.6@1229,1098.82
NetJ10_7: J10.7 R25.5 | length 143.5
  Top Layer L1 w15: R25.5@1030.57,1101.57 1129,1003.14 J10.7@1129,998.82
NetJ10_8: J10.8 R1.4 S1.4 U4.5 | length 1738
  Top Layer L1 w15: R1.4@663.09,731.24 715.85,784 918.5,784 968.5,834 S1.4@1113,834 1139,834 1229,924 J10.8@1229,998.82
  Top Layer L1 w23.62: U4.5@650,1609.73 v1(650,1644.39)
  Bottom Layer L4 w15: v1(650,1644.39) 650,1411.65 912.65,1149 964,1149 1064.18,1048.82 1179,1048.82 J10.8@1229,998.82
NetJ11_1: J11.1 R12.2 R13.1 U3.4 | length 241.1
  Top Layer L1 w15: R12.2@542.46,2043.77 R13.1@614.57,2043.77 ; J11.1@600,1940.76 R13.1@600,2043.77 ; R13.1@612.6,2043.77 U3.4@612.6,2109.73
NetJ15_1: J15.1 R15.2 R16.1 U4.4 | length 241.1
  Top Layer L1 w15: R15.2@542.46,1546.4 R16.1@614.57,1546.4 ; J15.1@600,1440.76 R16.1@600,1546.4 ; R16.1@612.6,1546.4 U4.4@612.6,1609.73
NetJ16_2: J16.2 J18.1 R2.2 U4.3 | length 751.8
  Top Layer L1 w15: J18.1@54.13,1718 U4.3@605.91,1718 ; 327,1718 J16.2@327,1918
NetR5_1: R5.1 U1.1 | length 63.5
  Top Layer L1 w15: U1.1@687.4,3218 R5.1@750.95,3218
NetR8_1: R8.1 U2.1 | length 63.5
  Top Layer L1 w15: U2.1@687.4,2718 R8.1@750.95,2718
NetR14_1: R14.1 U3.1 | length 63.5
  Top Layer L1 w15: U3.1@687.4,2218 R14.1@750.95,2218
NetR17_1: R17.1 U4.1 | length 63.5
  Top Layer L1 w15: U4.1@687.4,1718 R17.1@750.95,1718
NetR18_2: R18.2 R19.2 U6.2 U6.6 | length 476.1
  Top Layer L1 w15: U6.2@415,1307.28 415,1204 365,1154 365,1092.72 365,999.01 R18.2@402.01,962 R19.2@469.01,895
NetR25_1: R25.1 U8.6 | length 101.1
  Top Layer L1 w15: U8.6@897.29,1229.41 911.29,1229.41 917.07,1235.18 940.91,1235.18 979.39,1196.7 R25.1@979.39,1196.06
NetR25_2: R25.2 U8.4 | length 87.8
  Top Layer L1 w15: U8.4@897.29,1178.22 911.29,1178.22 924.95,1164.56 R25.2@979.39,1164.56
NetR25_3: R25.3 U7.6 | length 87.8
  Top Layer L1 w15: U7.6@897.29,1119.41 911.29,1119.41 924.95,1133.07 R25.3@979.39,1133.07
NetR25_4: R25.4 U7.4 | length 101.1
  Top Layer L1 w15: U7.4@897.29,1068.22 911.29,1068.22 917.07,1062.44 940.91,1062.44 979.39,1100.92 R25.4@979.39,1101.57
NetU5_1: U5.1 U6.1 | length 138.3
  Top Layer L1 w15: U6.1@465,1307.28 465,1263 515.2,1212.8 U5.1@538.24,1212.8
NetU5_2: U5.2 U6.7 | length 171.7
  Top Layer L1 w15: U6.7@415,1092.72 U6.7@415,1111 ; U6.7@416,1112 491.21,1187.21 U5.2@538.24,1187.21
NetU5_3: U5.3 U7.3 | length 313.9
  Top Layer L1 w15: U5.3@538.24,1161.61 590.3,1161.61 689.47,1062.44 788.93,1062.44 794.71,1068.22 U7.3@808.71,1068.22
NetU5_5: U5.5 U7.1 | length 121.8
  Top Layer L1 w15: U5.5@693.76,1136.02 760,1136.01 778.1,1136.01 794.71,1119.41 U7.1@808.71,1119.41
NetU5_6: U5.6 U8.3 | length 121.8
  Top Layer L1 w15: U5.6@693.76,1161.61 760,1161.61 778.1,1161.61 794.71,1178.22 U8.3@808.71,1178.22
NetU5_7: U5.7 U8.1 | length 137.2
  Top Layer L1 w15: U5.7@693.76,1187.21 717,1187.21 764.98,1235.18 788.93,1235.18 794.71,1229.41 U8.1@808.71,1229.41
VCC: C1.1 C2.1 C4.1 C6.1 C7.1 C10.1 C12.1 C14.2 J13.1 R18.1 S1.5 S1.6 S1.7 S1.8 U1.6 U2.6 U3.6 U4.6 U5.8 U6.8 U7.5 U8.5 | length 1082.1
  Top Layer L1 w15: U5.8@693.76,1212.8 v1(693.76,1239.13) ; U7.5@897.29,1093.81 v1(928.99,1093.81) ; U8.5@897.29,1203.81 v1(928.99,1203.81)
  Top Layer L1 w23.62: C12.1@465,1022.43 U6.8@465,1092.72 ; U4.6@687.4,1609.73 v1(714.18,1609.73) C4.1@743.96,1609.73 ; U3.6@687.4,2109.73 v1(714.18,2109.73) C10.1@743.96,2109.73 ; U2.6@687.4,2609.73 v1(714.18,2609.73) C6.1@743.96,2609.73 ; U1.6@687.4,3109.73 v1(714.18,3109.73) C7.1@743.96,3109.73 ; v1(693.76,1239.13) C14.2@693.76,1269.41
  Top Layer L1 w26: R18.1@465,962 v1(499.65,962) ; S1.8@774,534 v1(836.97,534) ; S1.7@774,634 v1(836.97,634) ; S1.6@774,734 v1(836.97,734) ; S1.5@774,834 v1(836.97,834) ; v1(975,3233.85) C2.1@975,3268.5 ; v1(1159.33,2170) C1.1@1193,2170 v1(1226.67,2170)
  Top Layer L1 w37.4: J13.1@1193,1893 C1.1@1193,2170
  other v1: 465,1049.21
